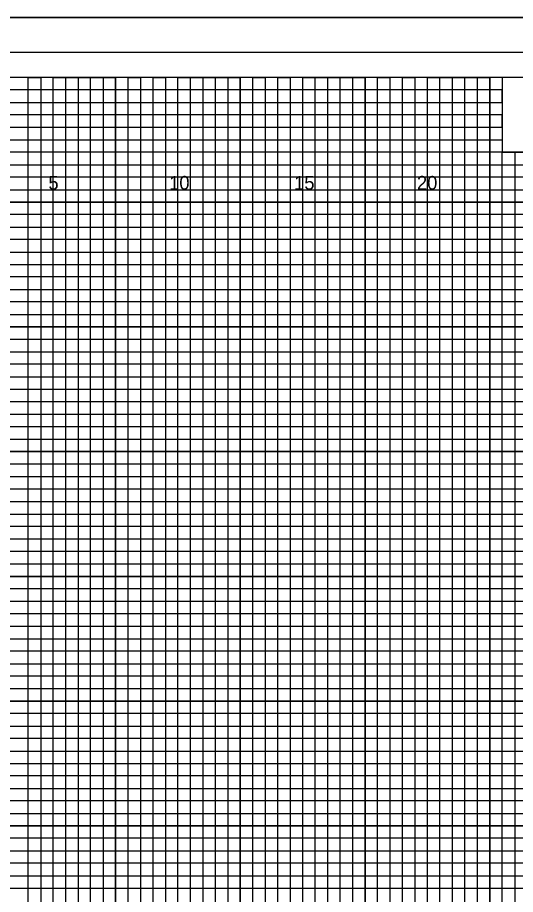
# Model space of a CAD drawing. Extents: x -4 to 103, y -2 to 138.
# Drawn here: x 54.82 to 74.78, y 32.25 to 67.4 of the extents above; entities that cross this region are included whole.
import ezdxf

# ---------------------------------------------------------------- set-up
doc = ezdxf.new("R2010")
doc.units = 0
for name, color, linetype in [('Exist XS Ground Line', 7, 'Continuous'), ('Old_Level_10', 7, 'Continuous'), ('Old_Level_16', 7, 'Continuous'), ('Old_Level_3', 7, 'Continuous'), ('Old_Level_5', 7, 'Continuous'), ('Old_Level_8', 7, 'Continuous'), ('Prop XS Elevation Labels', 7, 'Continuous'), ('Prop XS Finish Grade', 7, 'Continuous')]:
    doc.layers.add(name, color=color, linetype=linetype)

msp = doc.modelspace()

# ---------------------------------------------------------------- linework, layer by layer
at = {"layer": 'Exist XS Ground Line'}
msp.add_lwpolyline([(103, 66), (-2.8, 66), (-2.8, -1), (103, -1)], close=True, dxfattribs=at)
at = {"layer": 'Old_Level_10'}
for p, q in [((56.25, 0), (56.25, 65)), ((58.75, 0), (58.75, 65)), ((61.25, 0), (61.25, 65)), ((63.75, 0), (63.75, 65)), ((66.25, 0), (66.25, 65)), ((68.75, 0), (68.75, 65)), ((71.25, 0), (71.25, 65)), ((73.75, 0), (73.75, 65)), ((0, 62.5), (74.25, 62.5)), ((0, 60), (102.5, 60)), ((0, 57.5), (102.5, 57.5)), ((0, 55), (102.5, 55)), ((0, 52.5), (102.5, 52.5)), ((0, 50), (102.5, 50)), ((0, 47.5), (102.5, 47.5)), ((0, 45), (102.5, 45)), ((0, 42.5), (102.5, 42.5)), ((0, 40), (102.5, 40)), ((0, 37.5), (102.5, 37.5)), ((0, 35), (102.5, 35)), ((0, 32.5), (102.5, 32.5))]:
    msp.add_line(p, q, dxfattribs=at)
at = {"layer": 'Old_Level_3'}
msp.add_line((-3.5, 67.4), (103.4, 67.4), dxfattribs=at)
at = {"layer": 'Old_Level_5'}
msp.add_lwpolyline([(103.4, 67.4), (-3.5, 67.4), (-3.5, -2.425), (103.4, -2.425)], close=True, dxfattribs=at)
at = {"layer": 'Old_Level_8'}
for points in [[(56.25, 0), (56.25, 65), (58.75, 65), (58.75, 0)], [(61.25, 0), (61.25, 65), (63.75, 65), (63.75, 0)], [(66.25, 0), (66.25, 65), (68.75, 65), (68.75, 0)], [(71.25, 0), (71.25, 65), (73.75, 65), (73.75, 0)], [(0, 62.5), (74.25, 62.5)], [(0, 57.5), (102.5, 57.5), (102.5, 60), (0, 60)], [(0, 52.5), (102.5, 52.5), (102.5, 55), (0, 55)], [(0, 47.5), (102.5, 47.5), (102.5, 50), (0, 50)], [(0, 42.5), (102.5, 42.5), (102.5, 45), (0, 45)], [(0, 37.5), (102.5, 37.5), (102.5, 40), (0, 40)], [(0, 32.5), (102.5, 32.5), (102.5, 35), (0, 35)]]:
    msp.add_lwpolyline(points, dxfattribs=at)
at = {"layer": 'Prop XS Elevation Labels'}
for points in [[(102.5, 65), (0, 65), (0, 0), (102.5, 0)], [(83.75, 65), (74.25, 65), (74.25, 62), (83.75, 62)]]:
    msp.add_lwpolyline(points, close=True, dxfattribs=at)
at = {"layer": 'Prop XS Finish Grade'}
for points in [[(55.25, 0), (55.25, 65), (55.75, 65), (55.75, 0)], [(56.75, 0), (56.75, 65), (57.25, 65), (57.25, 0)], [(57.75, 0), (57.75, 65), (58.25, 65), (58.25, 0)], [(59.25, 0), (59.25, 65), (59.75, 65), (59.75, 0)], [(60.25, 0), (60.25, 65), (60.75, 65), (60.75, 0)], [(61.75, 0), (61.75, 65), (62.25, 65), (62.25, 0)], [(62.75, 0), (62.75, 65), (63.25, 65), (63.25, 0)], [(64.25, 0), (64.25, 65), (64.75, 65), (64.75, 0)], [(65.25, 0), (65.25, 65), (65.75, 65), (65.75, 0)], [(66.75, 0), (66.75, 65), (67.25, 65), (67.25, 0)], [(67.75, 0), (67.75, 65), (68.25, 65), (68.25, 0)], [(69.25, 0), (69.25, 65)], [(69.25, 65), (69.75, 65), (69.75, 0)], [(70.25, 0), (70.25, 65), (70.75, 65), (70.75, 0)], [(71.75, 0), (71.75, 65), (72.25, 65), (72.25, 0)], [(72.75, 0), (72.75, 65), (73.25, 65), (73.25, 0)], [(0, 62), (0, 63), (74.25, 63), (74.25, 63.5), (0, 63.5), (0, 64), (74.25, 64), (74.25, 64.5), (0, 64.5)], [(0, 61.5), (102.5, 61.5), (102.5, 62), (0, 62)], [(74.25, 0), (74.25, 62), (74.75, 62), (74.75, 0)], [(0, 60.5), (102.5, 60.5), (102.5, 61), (0, 61)], [(0, 59), (102.5, 59), (102.5, 59.5), (0, 59.5)], [(0, 58), (102.5, 58), (102.5, 58.5), (0, 58.5)], [(0, 56.5), (102.5, 56.5), (102.5, 57), (0, 57)], [(0, 55.5), (102.5, 55.5), (102.5, 56), (0, 56)], [(0, 54), (102.5, 54), (102.5, 54.5), (0, 54.5)], [(0, 53), (102.5, 53), (102.5, 53.5), (0, 53.5)], [(0, 51.5), (102.5, 51.5), (102.5, 52), (0, 52)], [(0, 50.5), (102.5, 50.5), (102.5, 51), (0, 51)], [(0, 49), (102.5, 49), (102.5, 49.5), (0, 49.5)], [(0, 48), (102.5, 48), (102.5, 48.5), (0, 48.5)], [(0, 46.5), (102.5, 46.5), (102.5, 47), (0, 47)], [(0, 45.5), (102.5, 45.5), (102.5, 46), (0, 46)], [(0, 44), (102.5, 44), (102.5, 44.5), (0, 44.5)], [(0, 43), (102.5, 43), (102.5, 43.5), (0, 43.5)], [(0, 41.5), (102.5, 41.5), (102.5, 42), (0, 42)], [(0, 40.5), (102.5, 40.5), (102.5, 41), (0, 41)], [(0, 39), (102.5, 39), (102.5, 39.5), (0, 39.5)], [(0, 38), (102.5, 38), (102.5, 38.5), (0, 38.5)], [(0, 36.5), (102.5, 36.5), (102.5, 37), (0, 37)], [(0, 35.5), (102.5, 35.5), (102.5, 36), (0, 36)], [(0, 34), (102.5, 34), (102.5, 34.5), (0, 34.5)], [(0, 33), (102.5, 33), (102.5, 33.5), (0, 33.5)]]:
    msp.add_lwpolyline(points, dxfattribs=at)

# ---------------------------------------------------------------- texts
at = {"layer": 'Old_Level_16'}
for s, p in [('5', (56.057, 60.5)), ('10', (60.897, 60.5)), ('15', (65.906, 60.5)), ('20', (70.831, 60.5))]:
    msp.add_text(s, height=0.55, dxfattribs=at).set_placement(p)

doc.saveas('drawing.dxf')
